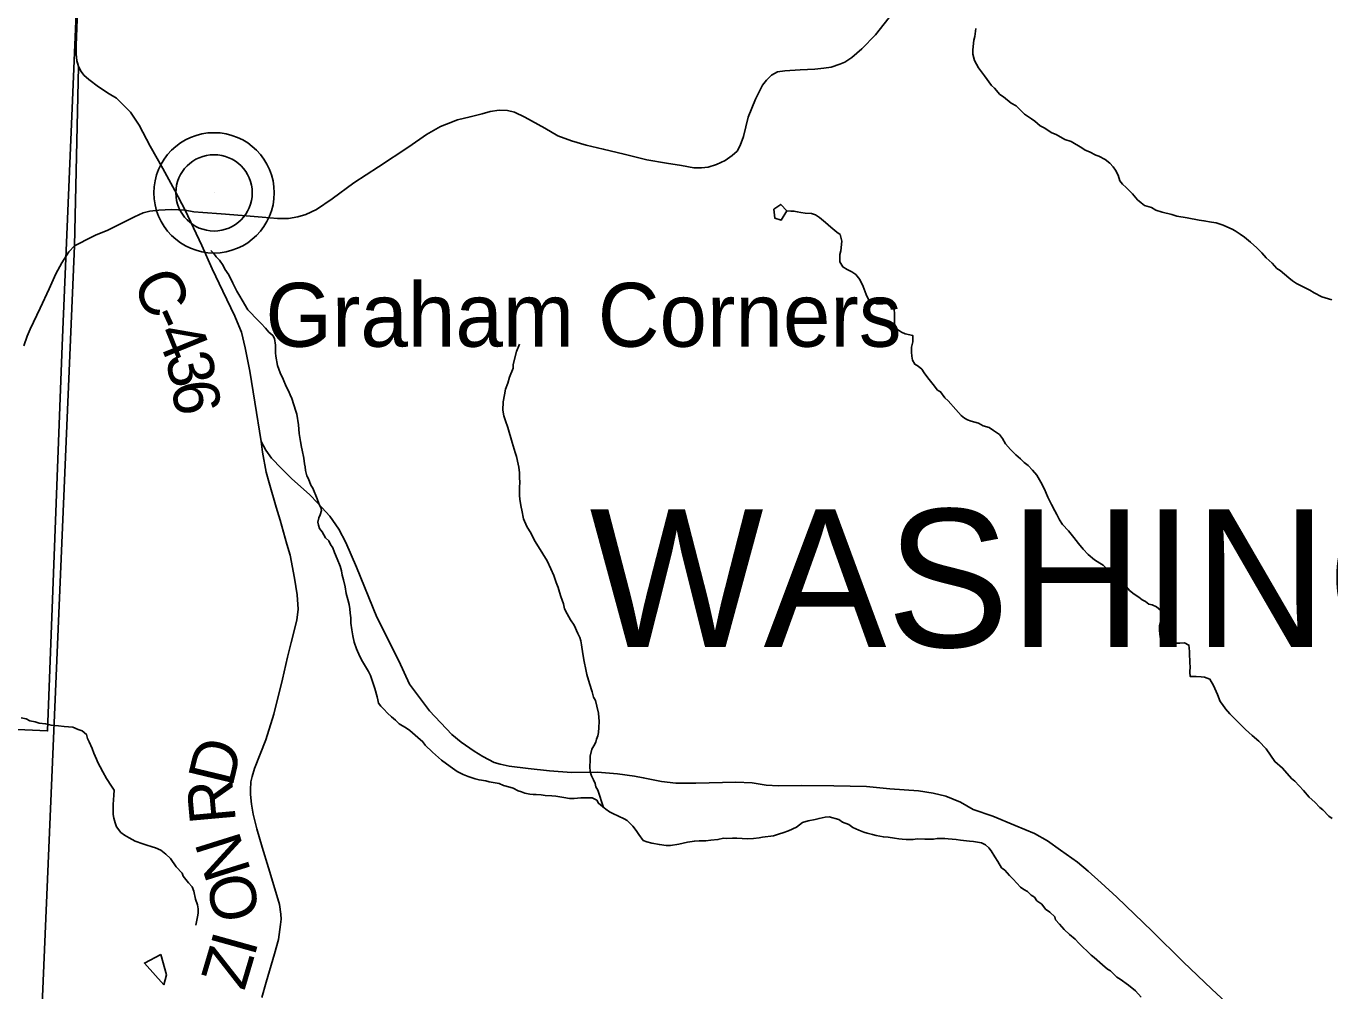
# Model space of a CAD drawing. Extents: x 0 to 34, y 0 to 22.
# Drawn here: x 26.261 to 27.873, y 18.646 to 19.839 of the extents above; entities that cross this region are included whole.
import ezdxf

# ---------------------------------------------------------------- set-up
doc = ezdxf.new("R2010")
doc.units = 0
for name, color, linetype in [('GM_X_County_Road', 7, 'Continuous'), ('GM_X_County_Road_Text', 7, 'Continuous'), ('GM_X_Minor_Lake', 7, 'Continuous'), ('GM_X_Minor_River', 7, 'Continuous'), ('GM_X_Section', 7, 'Continuous'), ('GM_X_Township', 7, 'Continuous'), ('GM_X_Township_Road', 7, 'Continuous'), ('GM_X_Township_Text', 7, 'Continuous'), ('GM_X_Unincorporated', 7, 'Continuous'), ('GM_X_Unincorporated_Location', 7, 'Continuous'), ('GM_X_Unincorporated_Text', 7, 'Continuous')]:
    doc.layers.add(name, color=color, linetype=linetype)

msp = doc.modelspace()

# ---------------------------------------------------------------- linework, layer by layer
at = {"layer": 'GM_X_County_Road'}
for points in [[(26.3405, 20.399), (26.3407, 20.3932), (26.3403, 20.3674), (26.336, 20.2481), (26.3348, 20.2025), (26.3299, 20.0679), (26.326, 19.9813), (26.325, 19.9211), (26.3245, 19.8669), (26.3238, 19.8473), (26.3228, 19.8154), (26.3228, 19.8045), (26.3235, 19.7961), (26.3245, 19.7924)], [(27.3324, 19.8553), (27.3108, 19.8283), (27.2939, 19.8108), (27.2815, 19.8002), (27.2732, 19.7944), (27.2667, 19.7919), (27.2563, 19.7884), (27.2469, 19.7868), (27.236, 19.7857), (27.2178, 19.7847), (27.1989, 19.7838), (27.1899, 19.7824), (27.1823, 19.7785), (27.1761, 19.7721), (27.1713, 19.7658), (27.1627, 19.7485), (27.1533, 19.7262), (27.1477, 19.7024), (27.1436, 19.6914), (27.1397, 19.6842), (27.1339, 19.6791), (27.1251, 19.6729), (27.1143, 19.6678), (27.1039, 19.6644), (27.0956, 19.6637), (27.0864, 19.6639), (27.071, 19.6667), (27.0525, 19.6695), (27.0281, 19.6738), (27, 19.6805), (26.9744, 19.687), (26.9534, 19.6918), (26.9349, 19.6971), (26.9183, 19.7034), (26.902, 19.7128), (26.8773, 19.7264), (26.8644, 19.7324), (26.8559, 19.7347), (26.8455, 19.7349), (26.8347, 19.7333), (26.8248, 19.7304), (26.8097, 19.7269), (26.7943, 19.7232), (26.7805, 19.7179), (26.7731, 19.7147), (26.7556, 19.705), (26.7339, 19.6898), (26.6963, 19.6651), (26.6661, 19.645), (26.6391, 19.6254), (26.6199, 19.6121), (26.6067, 19.6061), (26.5967, 19.6031), (26.585, 19.6012), (26.5714, 19.6012), (26.5527, 19.6027), (26.5277, 19.6046), (26.502, 19.6068), (26.4791, 19.6086), (26.468, 19.6095), (26.4574, 19.6114)], [(26.3245, 19.7924), (26.3254, 19.7889), (26.3288, 19.7829), (26.3321, 19.7783), (26.3381, 19.7729), (26.3502, 19.7639), (26.3633, 19.7554), (26.3726, 19.7498), (26.3809, 19.7418), (26.3896, 19.7325), (26.4004, 19.7164), (26.4143, 19.6906), (26.4296, 19.6629), (26.4446, 19.6356), (26.4574, 19.6114), (26.4778, 19.5676), (26.4909, 19.5389), (26.504, 19.5114), (26.5189, 19.4805), (26.5217, 19.4735), (26.527, 19.4604), (26.5316, 19.4413), (26.5373, 19.4122), (26.5437, 19.3741), (26.5513, 19.3254), (26.5572, 19.3148), (26.564, 19.3046), (26.5765, 19.2919), (26.5894, 19.279), (26.6111, 19.2596), (26.6214, 19.2489), (26.6361, 19.2329), (26.6475, 19.2168), (26.6561, 19.2003), (26.6692, 19.1701), (26.6945, 19.1081), (26.7214, 19.0543), (26.7346, 19.0252), (26.7593, 18.9923), (26.7871, 18.9629), (26.7986, 18.9537), (26.8147, 18.9423), (26.8253, 18.9358), (26.8394, 18.9286), (26.847, 18.9264), (26.8581, 18.9237), (26.8813, 18.9208), (26.908, 18.9182), (26.9349, 18.916), (26.9673, 18.9163), (26.992, 18.9143), (27.0128, 18.9116), (27.0237, 18.9095), (27.0464, 18.9049), (27.0639, 18.9029), (27.0889, 18.9029), (27.1384, 18.9039), (27.1585, 18.9031), (27.1759, 18.9005), (27.1912, 18.8995), (27.2189, 18.8999), (27.2595, 18.8997), (27.2997, 18.8987), (27.3288, 18.8958), (27.3643, 18.8932), (27.3822, 18.8904), (27.3981, 18.8868), (27.416, 18.8794), (27.4318, 18.8703), (27.4561, 18.8619), (27.4836, 18.8507), (27.5077, 18.8408), (27.5236, 18.8314), (27.5397, 18.8201), (27.5606, 18.8051), (27.5738, 18.794), (27.5901, 18.7798), (27.6094, 18.7619), (27.653, 18.7197), (27.6915, 18.6819), (27.7267, 18.6482), (27.7441, 18.6319)], [(26.552, 18.6379), (26.5576, 18.6567), (26.5679, 18.692), (26.5727, 18.7094), (26.5754, 18.7279), (26.5761, 18.7345), (26.5757, 18.7409), (26.574, 18.7528), (26.5669, 18.7762), (26.5605, 18.7982), (26.5525, 18.8238), (26.5459, 18.8465), (26.5413, 18.8646), (26.5395, 18.877), (26.5382, 18.889), (26.538, 18.8946), (26.5387, 18.9044), (26.5401, 18.9109), (26.5431, 18.9212), (26.557, 18.9564), (26.5672, 18.9881), (26.5778, 19.0315), (26.5838, 19.0585), (26.5884, 19.0766), (26.5955, 19.1045), (26.597, 19.1182), (26.5957, 19.1357), (26.5927, 19.1565), (26.5871, 19.1849), (26.583, 19.1983), (26.5747, 19.228), (26.5699, 19.2442), (26.5614, 19.2743), (26.5577, 19.2876), (26.5529, 19.312), (26.5513, 19.3254)]]:
    msp.add_lwpolyline(points, dxfattribs=at)
at = {"layer": 'GM_X_Minor_Lake'}
for points in [[(27.2013, 19.6105), (27.1937, 19.6185), (27.1854, 19.6128)], [(27.1854, 19.6128), (27.1865, 19.6014), (27.1945, 19.5991), (27.2013, 19.6105)], [(26.4273, 18.691), (26.4069, 18.6804), (26.4308, 18.6535)], [(26.4308, 18.6535), (26.4342, 18.666), (26.4273, 18.691)]]:
    msp.add_lwpolyline(points, dxfattribs=at)
at = {"layer": 'GM_X_Minor_River'}
for points in [[(27.7557, 19.5859), (27.7519, 19.5878), (27.7455, 19.5908), (27.7409, 19.5927), (27.7322, 19.5957), (27.7265, 19.5964), (27.717, 19.5983), (27.7113, 19.5991), (27.6962, 19.6021), (27.6837, 19.6039), (27.6772, 19.6062), (27.6655, 19.6088), (27.6575, 19.6115), (27.6522, 19.6145), (27.6435, 19.6171), (27.6393, 19.6205), (27.6351, 19.6243), (27.6286, 19.6315), (27.621, 19.6395), (27.6165, 19.6436), (27.6131, 19.6478), (27.6108, 19.6546), (27.6077, 19.661), (27.6047, 19.6648), (27.6005, 19.6694), (27.5948, 19.6739), (27.5872, 19.6781), (27.5834, 19.6792), (27.5754, 19.6837), (27.5701, 19.6856), (27.5659, 19.6883), (27.5527, 19.6962), (27.5451, 19.6988), (27.5344, 19.7049), (27.5288, 19.7068), (27.5196, 19.7132), (27.5147, 19.7155), (27.5079, 19.7215), (27.5037, 19.7242), (27.4953, 19.7302), (27.4847, 19.7404), (27.4786, 19.7435), (27.4691, 19.7514), (27.4646, 19.7544), (27.4581, 19.7624), (27.4543, 19.7654), (27.4456, 19.7775), (27.4383, 19.7874), (27.4334, 19.7965), (27.4311, 19.8041), (27.4311, 19.8097), (27.4325, 19.8215), (27.4337, 19.8261), (27.4348, 19.8359)], [(27.6366, 19.1328), (27.6309, 19.1366), (27.6252, 19.1411), (27.6214, 19.1456), (27.6134, 19.154), (27.6096, 19.1566), (27.6032, 19.1638), (27.599, 19.1661), (27.5925, 19.1725), (27.5884, 19.1748), (27.5819, 19.1789), (27.5739, 19.1854), (27.5678, 19.1922), (27.5618, 19.1994), (27.5561, 19.2066), (27.5496, 19.2149), (27.542, 19.2229), (27.5386, 19.2285), (27.5351, 19.235), (27.5325, 19.2395), (27.5286, 19.2475), (27.5241, 19.2566), (27.5199, 19.2664), (27.5153, 19.2751), (27.5103, 19.2835), (27.505, 19.2899), (27.4997, 19.2956), (27.4948, 19.2994), (27.4902, 19.3039), (27.4845, 19.3088), (27.478, 19.3153), (27.4716, 19.3225), (27.4678, 19.3289), (27.4643, 19.3338), (27.4568, 19.3391), (27.4514, 19.3425), (27.4442, 19.3448), (27.4382, 19.3478), (27.4294, 19.3504), (27.4249, 19.3523), (27.4211, 19.3542), (27.4169, 19.3576), (27.4101, 19.3648), (27.4006, 19.3758), (27.3968, 19.3792), (27.3914, 19.3868), (27.3876, 19.389), (27.3823, 19.3959), (27.3755, 19.4042), (27.3713, 19.4102), (27.3682, 19.4148), (27.3637, 19.4186), (27.3595, 19.4208), (27.3568, 19.4258), (27.3557, 19.4307), (27.3553, 19.4356), (27.3556, 19.4421), (27.3571, 19.4485), (27.3571, 19.4565), (27.3476, 19.4584), (27.3431, 19.4606), (27.3393, 19.4629), (27.3351, 19.4674), (27.3343, 19.4716), (27.3343, 19.4838), (27.3339, 19.4887), (27.3331, 19.4982), (27.329, 19.497), (27.3244, 19.4959), (27.3202, 19.4955), (27.3127, 19.4955), (27.3085, 19.4974), (27.3024, 19.5008), (27.2994, 19.5072), (27.2959, 19.5171), (27.2917, 19.5258), (27.2868, 19.5318), (27.2815, 19.5352), (27.2758, 19.5382), (27.2705, 19.5413), (27.2667, 19.5473), (27.267, 19.5564), (27.2681, 19.561), (27.2692, 19.5731), (27.2673, 19.5811), (27.2631, 19.5841), (27.2559, 19.5905), (27.2491, 19.5962), (27.2415, 19.6023), (27.2369, 19.6057), (27.232, 19.6072), (27.224, 19.6075), (27.2187, 19.6083), (27.2142, 19.6094), (27.21, 19.6102), (27.2062, 19.6102), (27.2013, 19.6105)], [(27.8753, 19.5004), (27.8628, 19.5042), (27.8533, 19.5091), (27.848, 19.5125), (27.8313, 19.5208), (27.8264, 19.5238), (27.8222, 19.5276), (27.8112, 19.5367), (27.807, 19.5393), (27.8013, 19.5458), (27.7941, 19.5526), (27.7888, 19.5586), (27.7823, 19.5647), (27.7747, 19.5719), (27.7671, 19.5779), (27.7618, 19.5817), (27.7557, 19.5859)], [(26.6533, 19.1543), (26.6517, 19.16), (26.6506, 19.1653), (26.649, 19.171), (26.6452, 19.1801), (26.6422, 19.188), (26.6399, 19.1937), (26.6372, 19.1979), (26.6349, 19.2024), (26.6307, 19.2062), (26.6266, 19.2138), (26.6235, 19.2179), (26.6224, 19.2217), (26.6216, 19.2255), (26.6227, 19.2308), (26.6242, 19.2346), (26.6261, 19.2399), (26.6253, 19.2437), (26.623, 19.2475), (26.6204, 19.2544), (26.6154, 19.2676), (26.6127, 19.2714), (26.6097, 19.279), (26.6078, 19.2828), (26.6062, 19.2896), (26.6058, 19.2938), (26.6051, 19.2979), (26.6043, 19.3048), (26.602, 19.3146), (26.6012, 19.3184), (26.6001, 19.3252), (26.5985, 19.3351), (26.5977, 19.3461), (26.5954, 19.359), (26.5943, 19.3628), (26.5916, 19.3707), (26.5893, 19.3783), (26.5874, 19.3832), (26.5851, 19.3878), (26.5824, 19.3935), (26.5786, 19.4026), (26.5748, 19.4101), (26.5714, 19.4192), (26.5694, 19.431), (26.569, 19.4348), (26.569, 19.4446), (26.5678, 19.4526), (26.5659, 19.4564), (26.561, 19.4606), (26.5568, 19.4655), (26.5515, 19.4712), (26.5443, 19.4784), (26.5386, 19.4844), (26.5348, 19.4882), (26.5279, 19.4999), (26.5249, 19.5052), (26.5214, 19.5113), (26.5165, 19.5212), (26.5115, 19.5314), (26.5066, 19.5386), (26.5043, 19.5431), (26.4997, 19.5496), (26.4959, 19.5537), (26.4929, 19.5579), (26.4891, 19.5613)], [(26.9747, 18.8728), (26.9678, 18.8943), (26.9651, 18.8985), (26.9644, 18.9023), (26.9621, 18.9068), (26.9598, 18.9121), (26.9582, 18.9171), (26.9579, 18.9231), (26.9582, 18.9315), (26.9582, 18.9364), (26.9604, 18.9448), (26.9627, 18.9489), (26.965, 18.9535), (26.9661, 18.9573), (26.9676, 18.9615), (26.9683, 18.9656), (26.9687, 18.9717), (26.9691, 18.9793), (26.9686, 18.9895), (26.9663, 18.9979), (26.9648, 19.0051), (26.9621, 19.0093), (26.9606, 19.0157), (26.9572, 19.0259), (26.9541, 19.0373), (26.9526, 19.0434), (26.9506, 19.0532), (26.9491, 19.0627), (26.9475, 19.0741), (26.9468, 19.079), (26.9452, 19.0828), (26.943, 19.0881), (26.9384, 19.0983), (26.9338, 19.1048), (26.9296, 19.1124), (26.9266, 19.1184), (26.925, 19.1245), (26.922, 19.1336), (26.9201, 19.1389), (26.9185, 19.1446), (26.9162, 19.151), (26.9132, 19.1597), (26.9097, 19.1677), (26.9048, 19.1776), (26.8995, 19.1866), (26.8941, 19.195), (26.8892, 19.2029), (26.885, 19.2116), (26.88, 19.2204), (26.8758, 19.2298), (26.8735, 19.2405), (26.8728, 19.2442), (26.8712, 19.2537), (26.8708, 19.259), (26.8708, 19.2697), (26.8711, 19.2738), (26.8707, 19.2818), (26.8707, 19.2867), (26.87, 19.2935), (26.8692, 19.2973), (26.8669, 19.3068), (26.8653, 19.3117), (26.863, 19.3201), (26.8615, 19.3243), (26.8562, 19.3428), (26.8535, 19.3508), (26.8512, 19.3572), (26.85, 19.3641), (26.8504, 19.3743), (26.8522, 19.383), (26.8534, 19.3902), (26.8564, 19.3974), (26.8586, 19.405), (26.8628, 19.416), (26.8631, 19.4206), (26.8669, 19.4365), (26.8706, 19.4456)], [(27.2032, 18.844), (27.1964, 18.8413), (27.1923, 18.8402), (27.1847, 18.8379), (27.1714, 18.836), (27.1669, 18.8352), (27.1601, 18.8344), (27.1521, 18.834), (27.1461, 18.8344), (27.1396, 18.8348), (27.1343, 18.8347), (27.1267, 18.8343), (27.1229, 18.8347), (27.1161, 18.8332), (27.1074, 18.8324), (27.101, 18.8316), (27.093, 18.8316), (27.087, 18.8312), (27.0786, 18.8297), (27.0676, 18.8274), (27.0574, 18.8259), (27.0521, 18.8258), (27.0438, 18.827), (27.0343, 18.8288), (27.0282, 18.8304), (27.0237, 18.8319), (27.0184, 18.8394), (27.0149, 18.8444), (27.0111, 18.8497), (27.0039, 18.8565), (27.0001, 18.8587), (26.9933, 18.8621), (26.9861, 18.8652), (26.9819, 18.8674), (26.9777, 18.8708), (26.9732, 18.8739), (26.9686, 18.878), (26.9663, 18.8818), (26.9606, 18.8848), (26.9466, 18.8848), (26.9383, 18.884), (26.9326, 18.884), (26.9254, 18.8851), (26.9155, 18.8866), (26.9106, 18.887), (26.9023, 18.8878), (26.8977, 18.8885), (26.8913, 18.8889), (26.8875, 18.8889), (26.8837, 18.8892), (26.8772, 18.8904), (26.8731, 18.8922), (26.8693, 18.8934), (26.8628, 18.8968), (26.8587, 18.8979), (26.8511, 18.8998), (26.8458, 18.9024), (26.8332, 18.9047), (26.8291, 18.9058), (26.8207, 18.9069), (26.8158, 18.9084), (26.8075, 18.9111), (26.801, 18.9137), (26.7938, 18.9171), (26.7851, 18.9235), (26.7744, 18.9315), (26.7634, 18.941), (26.7543, 18.9497), (26.7513, 18.9538), (26.7452, 18.9595), (26.7353, 18.9678), (26.7311, 18.9709), (26.722, 18.9761), (26.7174, 18.9807), (26.7125, 18.9849), (26.7076, 18.9894), (26.703, 18.9943), (26.6992, 18.9981), (26.6965, 19.0019), (26.6958, 19.0057), (26.6946, 19.0095), (26.6919, 19.0201), (26.6904, 19.025), (26.6866, 19.036), (26.6839, 19.0409), (26.679, 19.0493), (26.6767, 19.0534), (26.6733, 19.0595), (26.6691, 19.069), (26.6664, 19.0773), (26.6645, 19.0849), (26.6633, 19.0925), (26.6621, 19.1008), (26.6621, 19.1073), (26.6613, 19.113), (26.6609, 19.1183), (26.6602, 19.1236), (26.6586, 19.13), (26.6563, 19.1372), (26.6552, 19.1456), (26.6533, 19.1543)], [(27.8754, 18.8591), (27.8716, 18.8621), (27.864, 18.87), (27.8602, 18.8727), (27.8541, 18.8795), (27.8473, 18.8856), (27.84, 18.8939), (27.8294, 18.9052), (27.8252, 18.9086), (27.8142, 18.9215), (27.8047, 18.9295), (27.7994, 18.9374), (27.794, 18.9454), (27.7849, 18.9548), (27.7766, 18.962), (27.7686, 18.9692), (27.7492, 18.9885), (27.7439, 18.9949), (27.7401, 19.0003), (27.737, 19.004), (27.734, 19.0124), (27.729, 19.0237), (27.7244, 19.0313), (27.7176, 19.034), (27.7138, 19.0343), (27.7074, 19.0347), (27.7002, 19.0347), (27.6994, 19.04), (27.7001, 19.0472), (27.6998, 19.0514), (27.6997, 19.0552), (27.6993, 19.0605), (27.699, 19.0654), (27.6989, 19.07), (27.6985, 19.0737), (27.6929, 19.0764), (27.6872, 19.076), (27.6834, 19.076), (27.6773, 19.0756), (27.6656, 19.0744), (27.6633, 19.0813), (27.6625, 19.0869), (27.6621, 19.0926), (27.6621, 19.0979), (27.6636, 19.1044), (27.6655, 19.1124), (27.6639, 19.1162), (27.6582, 19.1207), (27.6529, 19.1233), (27.6491, 19.1241), (27.6446, 19.1275), (27.6408, 19.1294), (27.6366, 19.1328)], [(26.2544, 18.9835), (26.2608, 18.9824), (26.2654, 18.9798), (26.2718, 18.9787), (26.2768, 18.9771), (26.2847, 18.9764), (26.2916, 18.9745), (26.3007, 18.9738), (26.3079, 18.973), (26.3185, 18.9719), (26.3249, 18.9693), (26.3302, 18.9674), (26.3352, 18.9632), (26.3367, 18.9579), (26.3386, 18.9541), (26.3424, 18.9458), (26.3443, 18.9401), (26.3478, 18.9325), (26.3493, 18.9284), (26.3523, 18.9231), (26.3554, 18.917), (26.3603, 18.9087), (26.3664, 18.8992), (26.3695, 18.8943), (26.3691, 18.8882), (26.3684, 18.8764), (26.3684, 18.8643), (26.3692, 18.8594), (26.3707, 18.8537), (26.3723, 18.8487), (26.378, 18.8419), (26.3825, 18.8385), (26.3882, 18.8351), (26.3954, 18.8313), (26.4049, 18.8279), (26.4087, 18.8268), (26.4167, 18.8242), (26.4205, 18.8227), (26.4273, 18.82), (26.4334, 18.8151), (26.4391, 18.8098), (26.4463, 18.7996), (26.4535, 18.7916), (26.4547, 18.7878), (26.4615, 18.7795), (26.4661, 18.7746), (26.468, 18.7693), (26.4703, 18.7594), (26.4726, 18.7526), (26.4734, 18.7473), (26.4734, 18.7423), (26.4726, 18.7374), (26.4715, 18.7313), (26.4704, 18.7272)], [(27.6396, 18.6382), (27.6324, 18.6461), (27.6237, 18.6529), (27.6134, 18.6605), (27.6092, 18.6631), (27.6016, 18.6707), (27.5978, 18.673), (27.5917, 18.6783), (27.5815, 18.6874), (27.5777, 18.69), (27.5625, 18.7051), (27.5579, 18.7101), (27.5507, 18.7157), (27.5443, 18.7218), (27.5385, 18.7286), (27.5336, 18.7339), (27.5325, 18.7377), (27.5264, 18.7434), (27.5211, 18.7472), (27.5165, 18.7532), (27.5104, 18.7574), (27.5074, 18.7619), (27.5036, 18.7642), (27.499, 18.7687), (27.4945, 18.7714), (27.4903, 18.7744), (27.4812, 18.7843), (27.4766, 18.7888), (27.4709, 18.7952), (27.4667, 18.7983), (27.4622, 18.8062), (27.4584, 18.8119), (27.4538, 18.8191), (27.4511, 18.8229), (27.4469, 18.8267), (27.442, 18.8289), (27.4321, 18.8308), (27.4272, 18.8312), (27.4162, 18.8323), (27.4105, 18.833), (27.4007, 18.8342), (27.3965, 18.8345), (27.3874, 18.8345), (27.3825, 18.8337), (27.3719, 18.8337), (27.3624, 18.8341), (27.3575, 18.8333), (27.3488, 18.8333), (27.3439, 18.8337), (27.3397, 18.834), (27.3344, 18.8348), (27.3268, 18.8359), (27.3207, 18.8363), (27.3116, 18.8381), (27.3071, 18.8393), (27.3006, 18.8412), (27.2965, 18.8423), (27.2904, 18.8449), (27.2828, 18.8479), (27.2779, 18.8517), (27.2703, 18.8547), (27.2657, 18.8578), (27.2536, 18.8612), (27.2487, 18.8608), (27.2411, 18.8592), (27.2365, 18.8581), (27.2275, 18.8562), (27.2206, 18.8543), (27.2131, 18.8486), (27.2032, 18.844)]]:
    msp.add_lwpolyline(points, dxfattribs=at)
at = {"layer": 'GM_X_Section'}
msp.add_lwpolyline([(25.3473, 20.02), (26.3274, 19.9835), (26.3256, 19.9238), (26.3052, 19.4442), (26.2872, 18.9674), (25.2935, 19.0114)], close=True, dxfattribs=at)
at = {"layer": 'GM_X_Township'}
for points in [[(26.2579, 18.0444), (26.2775, 18.5614), (26.3204, 19.5672), (26.3254, 19.7889), (26.3235, 19.7961), (26.3228, 19.8045), (26.3228, 19.8154), (26.3238, 19.8473), (26.3245, 19.8669), (26.325, 19.9211), (26.326, 19.9813), (26.3403, 20.3674), (26.341, 20.3982), (26.344, 20.4298), (26.3517, 20.745), (26.352, 20.7571), (26.3529, 20.7844), (26.3538, 20.8148), (26.354, 20.8204), (26.3551, 20.8572), (26.3564, 20.9)], [(26.3564, 20.9), (26.3551, 20.8572), (26.354, 20.8204), (26.3538, 20.8148), (26.3529, 20.7844), (26.352, 20.7571), (26.3517, 20.745), (26.344, 20.4298), (26.341, 20.3982), (26.3403, 20.3674), (26.326, 19.9813), (26.325, 19.9211), (26.3245, 19.8669), (26.3238, 19.8473), (26.3228, 19.8154), (26.3228, 19.8045), (26.3235, 19.7961), (26.3254, 19.7889), (26.3204, 19.5672), (26.2775, 18.5614), (26.2579, 18.0444)]]:
    msp.add_lwpolyline(points, dxfattribs=at)
at = {"layer": 'GM_X_Township_Road'}
for points in [[(26.3474, 19.5807), (26.3611, 19.5863), (26.3781, 19.5947), (26.3948, 19.6033), (26.4056, 19.608), (26.4137, 19.6101), (26.4248, 19.6114), (26.4405, 19.612), (26.4492, 19.6117), (26.4574, 19.6114)], [(26.258, 19.4438), (26.2619, 19.4555), (26.2659, 19.4643), (26.2781, 19.4901), (26.2891, 19.5143), (26.2974, 19.5325), (26.305, 19.5462), (26.3136, 19.5599), (26.3204, 19.5672), (26.3423, 19.5786), (26.3474, 19.5807)]]:
    msp.add_lwpolyline(points, dxfattribs=at)
at = {"layer": 'GM_X_Unincorporated'}
for radius in [0.0744, 0.0472]:
    msp.add_circle((26.4931, 19.6328), radius, dxfattribs=at)
at = {"layer": 'GM_X_Unincorporated_Location'}
msp.add_line((26.4931, 19.6328), (26.4931, 19.6328), dxfattribs=at)

# ---------------------------------------------------------------- texts
at = {"layer": 'GM_X_County_Road_Text'}
for s, rotation, p in [('C', 294.6901, (26.3912, 19.523)), ('-', 294.5363, (26.4107, 19.4806)), ('4', 292.1319, (26.4201, 19.46)), ('3', 282.5, (26.4326, 19.43)), ('6', 278.9875, (26.44, 19.3967)), ('D', 76.4727, (26.5156, 18.8968)), ('R', 95.1277, (26.5202, 18.8552)), ('N', 107.4002, (26.5391, 18.7937)), ('O', 100.8003, (26.5502, 18.7377)), ('Z', 73.4725, (26.5304, 18.6452)), ('I', 74.4599, (26.5428, 18.6869))]:
    msp.add_text(s, height=0.0568, rotation=rotation, dxfattribs=at).set_placement(p)
at = {"layer": 'GM_X_Township_Text'}
msp.add_text('WASHINGTON', height=0.17045, rotation=0, dxfattribs=at).set_placement((26.9574, 19.0712))
at = {"layer": 'GM_X_Unincorporated_Text'}
msp.add_text('Graham Corners', height=0.078977, rotation=0, dxfattribs=at).set_placement((26.5567, 19.4425))

doc.saveas('drawing.dxf')
